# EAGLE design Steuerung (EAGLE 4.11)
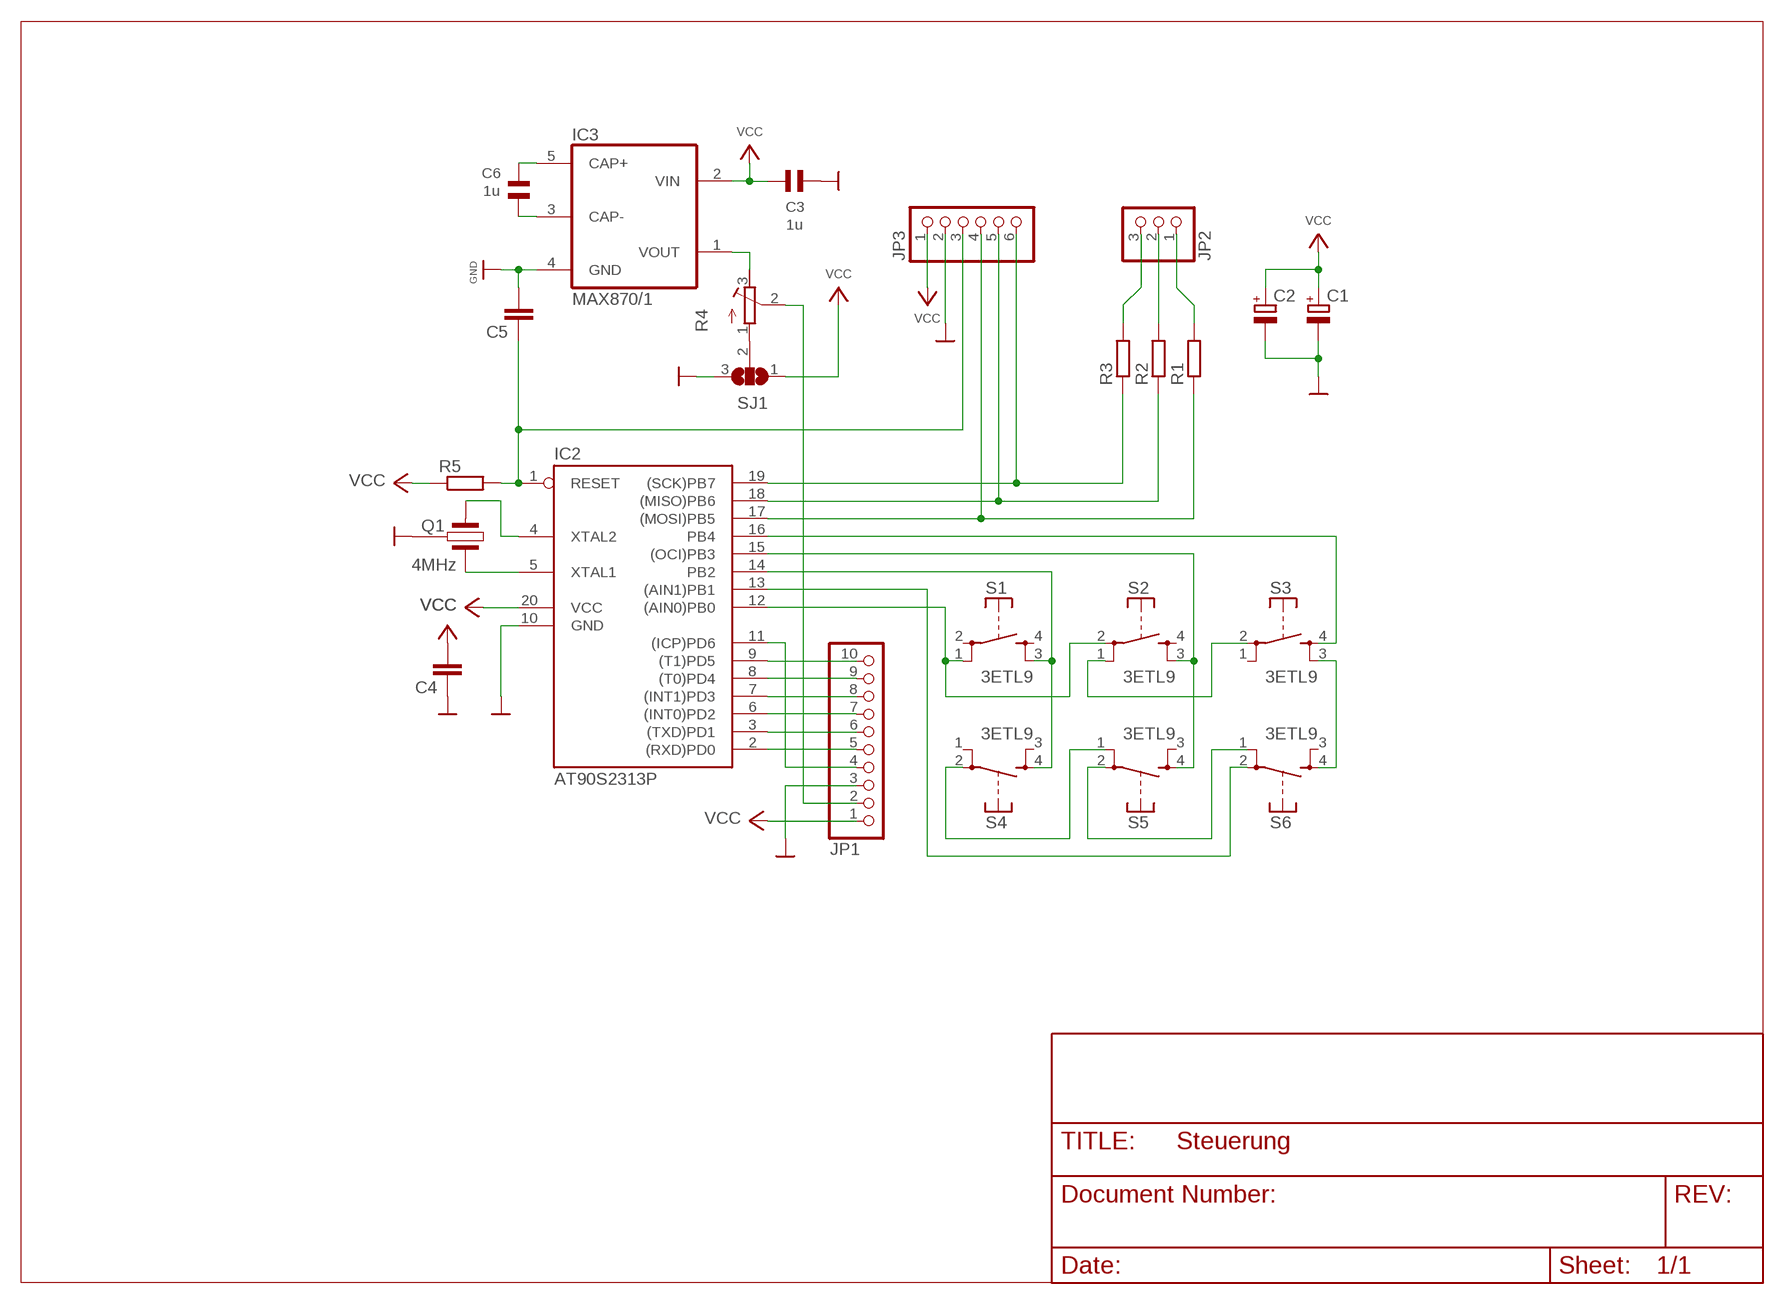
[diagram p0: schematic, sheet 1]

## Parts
C1  CPOL-EUE2-4  [E2-4]
C2  CPOL-EUE2-4  [E2-4]
C3  1u  C2,5  [1206]
C4  C-EU050-024X044  [C050-024X044]
C5  C-EU025-024X044  [C025-024X044]
C6  1u  C2,5  [1206]
IC2  AT90S2313P  [DIL20]
IC3  MAX870/1  [SOT-23/5]
JP1  PINHD-1X10  [1X10]
JP2  PINHD-1X3  [1X03]
JP3  PINHD-1X6  [1X06]
Q1  4MHz  CSB  [CSB]
R1  R-EU_0207/10  [0207/10]
R2  R-EU_0207/10  [0207/10]
R3  R-EU_0207/10  [0207/10]
R4  R-TRIMM74W  [RTRIM74W]
R5  R-EU_0207/10  [0207/10]
S1  3ETL9  [3ETL9]
S2  3ETL9  [3ETL9]
S3  3ETL9  [3ETL9]
S4  3ETL9  [3ETL9]
S5  3ETL9  [3ETL9]
S6  3ETL9  [3ETL9]
SJ1  SJ2W  [SJ_2]

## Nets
/RESET: C5.1 IC2.1(RESET) JP3.3 R5.2
GND: C1.- C2.- C3.2 C4.1 C5.2 IC2.10(GND) IC3.4(GND) JP1.3 JP3.2 Q1.2 SJ1.3
MISO: IC2.18((MISO)PB6) JP3.5 R2.1
MOSI: IC2.17((MOSI)PB5) JP3.4 R1.1
N$1: JP2.2 R2.2
N$2: JP2.1 R1.2
N$3: JP2.3 R3.2
N$4: JP1.2 R4.2(S)
N$5: IC2.4(XTAL2) Q1.1
N$8: S3.3 S6.4
N$10: IC2.16(PB4) S3.4
N$11: IC2.13((AIN1)PB1) S6.2
N$13: R4.1(E) SJ1.2
N$14: IC2.15((OCI)PB3) S2.3 S5.4
N$16: IC2.2((RXD)PD0) JP1.5
N$17: IC2.3((TXD)PD1) JP1.6
N$18: IC2.6((INT0)PD2) JP1.7
N$19: IC2.7((INT1)PD3) JP1.8
N$20: IC2.8((T0)PD4) JP1.9
N$21: IC2.9((T1)PD5) JP1.10
N$22: IC2.11((ICP)PD6) JP1.4
N$23: IC2.14(PB2) S1.3 S4.4
N$24: S4.2 S5.1
N$25: IC2.5(XTAL1) Q1.3
N$27: S5.2 S6.1
N$29: IC2.12((AIN0)PB0) S1.1 S2.2
N$30: S2.1 S3.2
N$31: C6.1 IC3.5(CAP+)
N$32: C6.2 IC3.3(CAP-)
SCK: IC2.19((SCK)PB7) JP3.6 R3.1
V-: IC3.1(VOUT) R4.3(A)
VCC: C1.+ C2.+ C3.1 C4.2 IC2.20(VCC) IC3.2(VIN) JP1.1 JP3.1 R5.1 SJ1.1
Unconnected: S1.2 S1.4 S2.4 S3.1 S4.1 S4.3 S5.3 S6.3

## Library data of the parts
C1 C2 = rcl:CPOL-EU: POLARIZED CAPACITOR, European symbol
C3 C6 = CAP:C2,5
C4 C5 = rcl:C-EU: CAPACITOR, European symbol
IC2 = atmel:AT90S2313: MICROCONTROLLER 2 Kbytes FLASH 128 bytes SRAM 128 bytes EEPROM UART
IC3 = maxim:MAX870/1
JP1 = pinhead:PINHD-1X10: PIN HEADER
JP2 = pinhead:PINHD-1X3: PIN HEADER
JP3 = pinhead:PINHD-1X6: PIN HEADER
Q1 = SPECIAL:CSB
R1-R3 R5 = rcl:R-EU_: RESISTOR, European symbol
R4 = rcl:R-TRIMM: Trimm resistor
S1-S6 = KEY:3ETL9
SJ1 = jumper:SJ2W: SMD solder JUMPER

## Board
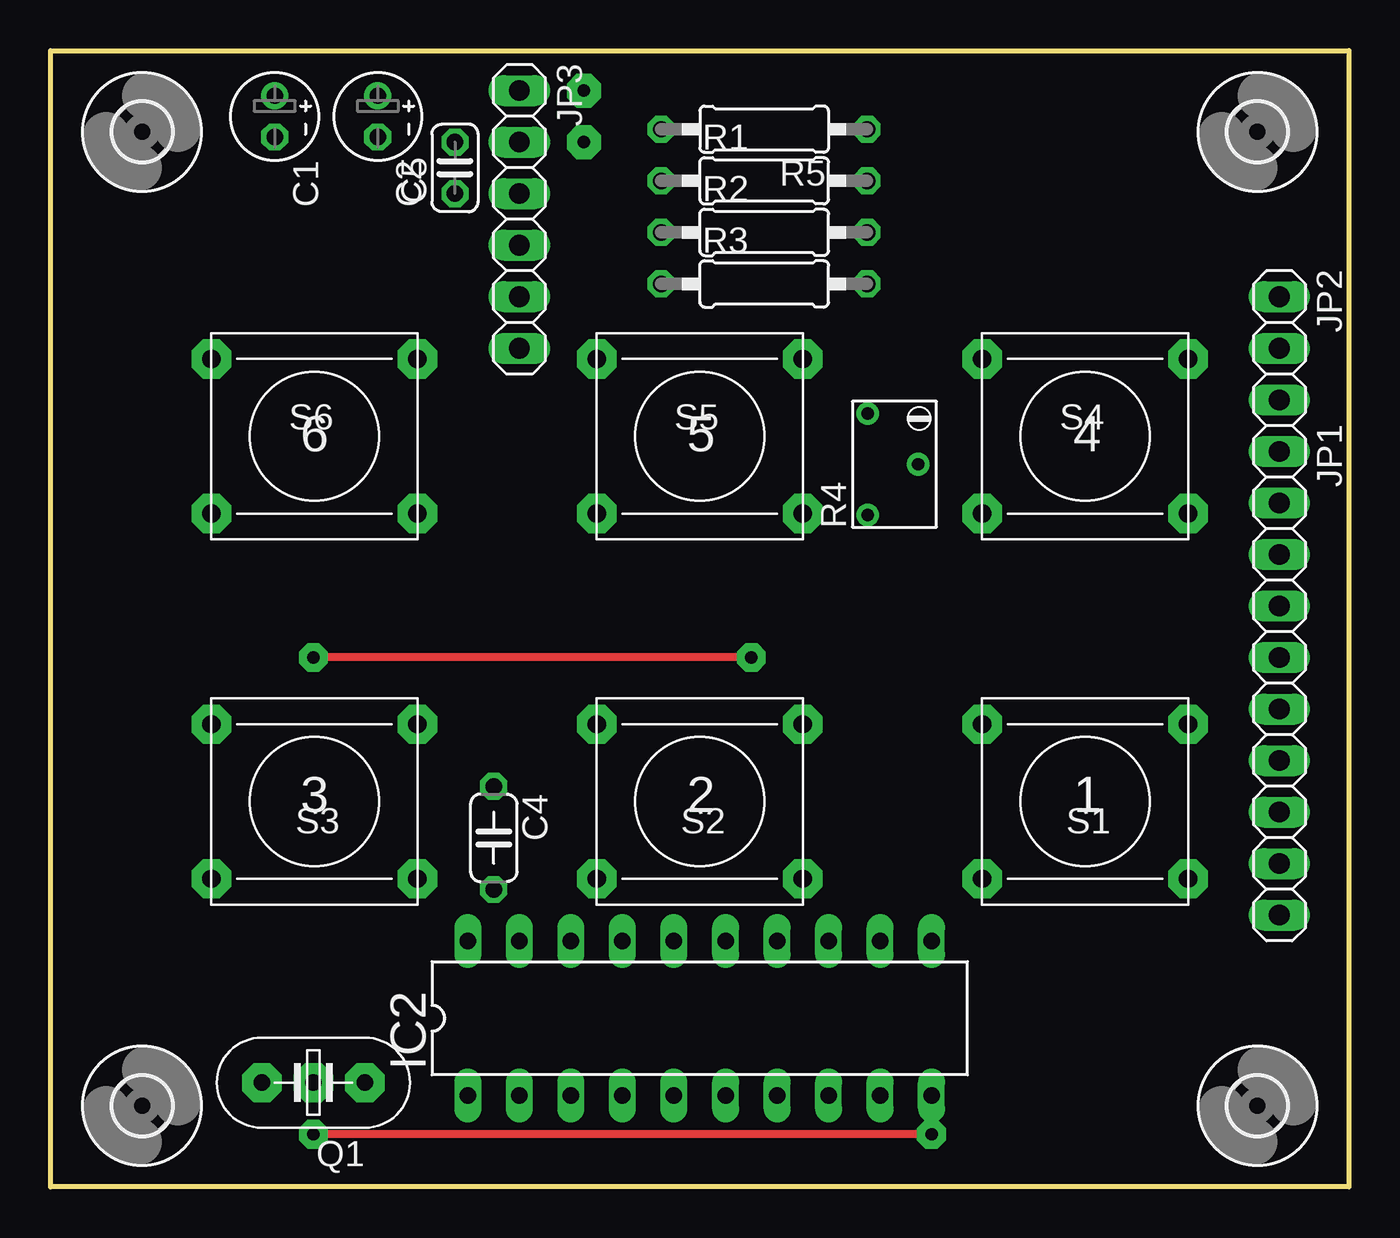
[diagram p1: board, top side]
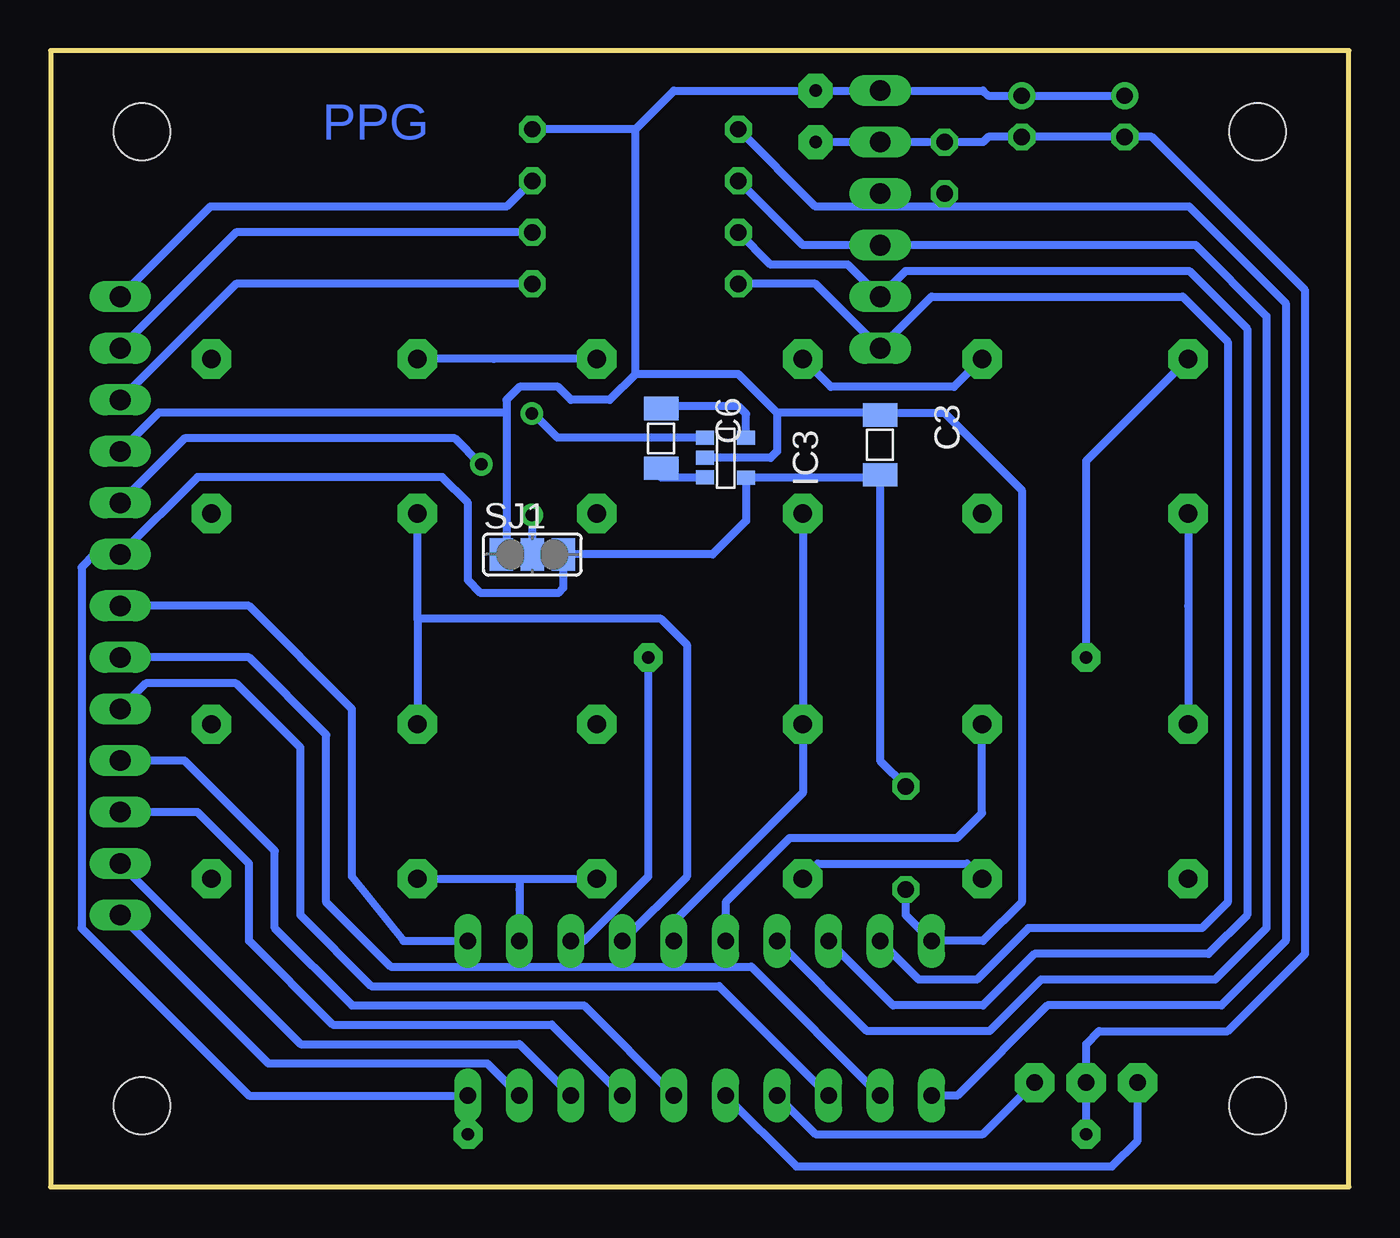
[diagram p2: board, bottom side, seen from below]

Size 64 x 56 mm. Coordinates in mm from the lower left corner, seen from the top.
Outline: 0,56 64,56 64,0 0,0 0,56
Copper layers (1*16): Top 0.035mm / dielectric 1.5mm / Bottom 0.035mm
Design rules "default": minimum track width 10mil, minimum drill 24mil, track to track 8mil, track to pad 8mil, pad to pad 8mil, via to via 8mil, smd to smd 8mil, copper to edge 40mil, drill to drill 8mil, minimum pad ring 10mil, minimum via ring 8mil, stop-mask expansion 4mil, vias tented up to drill 0mil, thermal gap 10mil

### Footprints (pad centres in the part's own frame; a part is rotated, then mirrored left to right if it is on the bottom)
E2-4 = drill 0.813 pad 1.27 round: + -1.016,0 | drill 0.813 pad 1.27 octagon: - 1.016,0
1206 = smd 1.143 x 1.702: 1 -1.473,0; 2 1.473,0
C050-024X044 = drill 0.813 octagon: 1 -2.54,0; 2 2.54,0
C025-024X044 = drill 0.813 octagon: 1 -1.27,0; 2 1.27,0
DIL20 = drill 0.813 long: 1 -11.43,-3.81; 2 -8.89,-3.81; 3 -6.35,-3.81; 4 -3.81,-3.81; 5 -1.27,-3.81; 6 1.27,-3.81; 7 3.81,-3.81; 8 6.35,-3.81; 9 8.89,-3.81; 10 11.43,-3.81; 11 11.43,3.81; 12 8.89,3.81; 13 6.35,3.81; 14 3.81,3.81; 15 1.27,3.81; 16 -1.27,3.81; 17 -3.81,3.81; 18 -6.35,3.81; 19 -8.89,3.81; 20 -11.43,3.81
SOT-23/5 = smd 0.686 x 0.889: 1 -0.991,-1.016; 2 0,-1.016; 3 0.965,-1.016; 4 0.991,1.016; 5 -0.99,1.016
1X10 = drill 1.016 long: 1 -11.43,0; 2 -8.89,0; 3 -6.35,0; 4 -3.81,0; 5 -1.27,0; 6 1.27,0; 7 3.81,0; 8 6.35,0; 9 8.89,0; 10 11.43,0
1X03 = drill 1.016 long: 1 -2.54,0; 2 0,0; 3 2.54,0
1X06 = drill 1.016 long: 1 -6.35,0; 2 -3.81,0; 3 -1.27,0; 4 1.27,0; 5 3.81,0; 6 6.35,0
CSB = drill 0.813 pad 1.93 octagon: 1 0,-2.54; 2 0,0; 3 0,2.54
0207/10 = drill 0.813 octagon: 1 -5.08,0; 2 5.08,0
RTRIM74W = drill 0.61 round: 1 -1.25,-2.5; 2 1.25,0; 3 -1.25,2.5
3ETL9 = drill 0.9 pad 1.93 octagon: 1 5.08,3.81; 2 -5.08,3.81; 3 5.08,-3.81; 4 -5.08,-3.81
SJ_2 = smd 1.168 x 1.6: 1 -1.524,0; 2 0,0; 3 1.524,0
2,8 = hole 2.8: 0,0

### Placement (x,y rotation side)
C1  11.05,52.77 270 top
C2  16.12,52.77 270 top
C3  23.11,36.57 270 bottom
C4  21.84,17.2 270 top
C5  19.94,50.23 90 top
C6  33.91,36.89 270 bottom
IC2  32,8.32 0 top
IC3  30.73,35.94 270 bottom
JP1  60.58,24.82 270 top
JP2  60.58,41.34 270 top
JP3  23.11,47.69 270 top
Q1  12.95,5.14 90 top
R1  35.17,49.59 0 top
R2  35.17,47.05 0 top
R3  35.17,44.51 0 top
R4  41.52,35.62 0 top
R5  35.17,52.13 180 top
S1  51,19 180 top
S2  32,19 180 top
S3  13,19 180 top
S4  51,37 0 top
S5  32,37 0 top
S6  13,37 0 top
SJ1  40.26,31.18 0 bottom
U$1  [2,8]  4.5,52 0 top
U$2  [2,8]  59.5,52 0 top
U$3  [2,8]  59.5,4 0 top
U$4  [2,8]  4.5,4 0 top

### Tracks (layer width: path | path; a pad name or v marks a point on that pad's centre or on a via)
/RESET
  Bottom 0.406: IC2.1 19.3,4.5 14.86,8.95 6.28,8.95 3.11,12.12 3.11,43.56 7.87,48.32 19.94,48.32 | 19.94,48.32 23.11,48.32 | 23.11,48.32 26.29,48.32 R5.2 | 19.94,48.32 C5.1 | 23.11,48.32 JP3.3
GND  (via drill 0.61 pad 1.42, 0.61 pad 1.68)
  Top 0.406: v43.43,2.6 v12.95,2.6
  Bottom 0.406: v43.43,2.6 IC2.10 54.23,4.5 62.48,12.76 62.48,30.54 61.84,31.18 JP1.3 56.77,34.98 44.7,34.98 43.43,33.72 43.43,29.91 42.8,29.27 38.98,29.27 38.73,29.52 SJ1.3 31.36,31.18 29.71,32.83 IC3.4 23.11,34.95 | v12.95,2.6 Q1.2 12.95,7.05 12.32,7.68 5.96,7.68 2.16,11.49 2.16,44.19 9.71,51.75 C1.- C2.- 17.78,51.75 18.03,51.5 C5.2 JP3.2 v26.29,51.5 | 23.11,34.95 23.07,34.95 | C4.1 23.11,21.02 23.11,34.95 | C3.2 23.11,34.95
MISO
  Bottom 0.406: IC2.18 22.48,8.95 18.03,8.95 15.49,11.49 6.92,11.49 5.01,13.39 5.01,42.29 7.87,45.14 21.84,45.14 JP3.5 24.7,45.46 28.51,45.46 R2.1
MOSI
  Bottom 0.406: IC2.17 23.74,7.68 17.71,7.68 15.17,10.22 6.6,10.22 4.06,12.76 4.06,42.92 7.55,46.41 JP3.4 26.92,46.41 R1.1
N$1
  Bottom 0.406: JP2.2 54.86,47.05 R2.2
N$2
  Bottom 0.406: R1.2 41.52,48.32 56.13,48.32 JP2.1
N$3
  Bottom 0.406: JP2.3 54.86,44.51 R3.2
N$4
  Bottom 0.406: JP1.2 57.4,36.89 44.06,36.89 42.8,35.62 R4.2
N$5
  Bottom 0.406: IC2.4 26.29,2.6 18.03,2.6 Q1.1
N$8
  Bottom 0.406: S6.4 7.92,28.64 S3.3
N$10
  Bottom 0.406: IC2.16 30.73,14.03 27.55,17.2 19.3,17.2 18.08,18.43 S3.4
N$11  (via drill 0.61 pad 1.42)
  Top 0.406: v34.54,26.09 v12.95,26.09
  Bottom 0.406: IC2.13 37.72,12.12 34.54,15.3 v34.54,26.09 | S6.2 12.95,35.78 v12.95,26.09
N$13
  Bottom 0.406: R4.1 40.26,33.12 SJ1.2
N$14
  Bottom 0.406: S5.4 S2.3 26.92,19.43 33.27,13.08 IC2.15
N$16
  Bottom 0.406: IC2.2 29.46,10.86 47.24,10.86 50.41,14.03 50.41,22.29 54.23,26.09 JP1.5
N$17
  Bottom 0.406: IC2.3 31.05,9.9 48.19,9.9 51.69,13.39 51.69,21.65 54.86,24.82 59.3,24.82 JP1.6
N$18
  Bottom 0.406: IC2.6 37.72,8.95 49.14,8.95 52.95,12.76 52.95,16.57 57.4,21.02 JP1.7
N$19
  Bottom 0.406: IC2.7 39.3,8 50.1,8 54.23,12.12 54.23,15.94 56.77,18.48 JP1.8
N$20
  Bottom 0.406: IC2.8 40.89,7.05 51.69,7.05 JP1.9
N$21
  Bottom 0.406: IC2.9 42.48,6.09 53.27,6.09 JP1.10
N$22
  Bottom 0.406: IC2.11 46.61,12.12 49.14,15.3 49.14,23.55 54.23,28.64 JP1.4
N$23
  Bottom 0.406: 45.92,28 S1.3 | 45.92,28 S4.4 | IC2.14 32.63,15.3 32.63,26.73 33.91,28 45.92,28
N$24
  Bottom 0.406: S4.2 42.16,40.81 S5.1
N$25
  Bottom 0.406: IC2.5 27.24,1.01 11.68,1.01 10.41,2.28 Q1.3
N$26  (via drill 0.61 pad 2.18)
  other vias: 4.5,52
N$27
  Bottom 0.406: S6.1 19.46,39.43 25.54,39.43 S5.2
N$28  (via drill 0.61 pad 2.18)
  other vias: 59.5,52
N$29
  Bottom 0.406: IC2.12 40.89,14.66 40.89,15.19 | 40.89,15.19 S2.2 | S1.1 40.89,15.19
N$30
  Bottom 0.406: S3.2 18.82,15.94 26.18,15.94 S2.1
N$31
  Bottom 0.406: IC3.5 29.71,38.1 30.09,38.48 33.91,38.48 C6.1
N$32
  Bottom 0.406: IC3.3 33.91,34.97 C6.2
N$33  (via drill 0.61 pad 2.18)
  other vias: 59.5,4
N$34  (via drill 0.61 pad 2.18)
  other vias: 4.5,4
SCK
  Bottom 0.406: IC2.19 21.2,10.22 18.35,10.22 15.81,12.76 7.23,12.76 5.96,14.03 5.96,41.65 8.19,43.88 20.57,43.88 JP3.6 26.29,44.51 R3.1
V-
  Bottom 0.406: R4.3 40.27,38.14 40.26,38.16 39.02,36.93 IC3.1
VCC  (via drill 0.61 pad 1.68)
  Bottom 0.406: C4.2 21.84,13.39 IC2.20 18.03,12.12 16.12,14.03 16.12,34.35 19.94,38.16 23.11,38.16 | 28.19,36.26 | 28.19,38.16 28.19,36.26 | 28.19,38.16 30.09,40.06 35.17,40.06 | 35.17,40.06 36.45,38.8 38.35,38.8 38.98,39.43 40.89,39.43 41.52,38.8 41.52,38.16 | 41.52,38.16 58.67,38.16 JP1.1 | C1.+ C2.+ 17.78,53.78 18.03,54.03 JP3.1 v26.29,54.03 33.27,54.03 35.17,52.13 | 35.17,40.06 35.17,52.13 | IC3.2 28.51,35.94 28.19,36.26 | C3.1 23.11,38.16 | 23.11,38.16 28.19,38.16 | 35.17,52.13 R5.1 | SJ1.1 41.52,31.18 41.52,38.16

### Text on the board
Bottom: PPG
tPlace: 6 | 5 | 4 | 3 | 2 | 1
